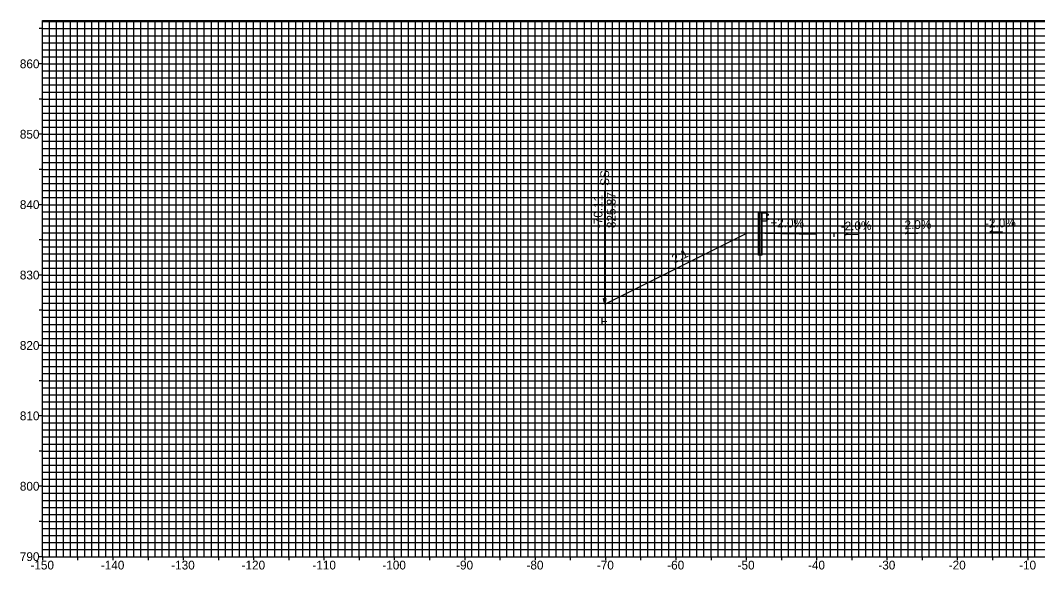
# Model space of a CAD drawing. Extents: x -153 to 153, y 788 to 866.
# Drawn here: x -153.1 to -8.6, y 788.2 to 866.2 of the extents above; entities that cross this region are included whole.
import ezdxf

# ---------------------------------------------------------------- set-up
doc = ezdxf.new("R2010")
doc.units = 0
for name, color, linetype in [('Exist Utilities Power Transformer CELL', 7, 'Continuous'), ('P_NCDOT_XS_Label_Grading_Side_Slope', 7, 'Continuous'), ('P_NCDOT_XS_Label_Slope_Superelevation', 7, 'Continuous'), ('P_NCDOT_XS_Leader_Line', 7, 'Continuous'), ('P_NCDOT_XS_Sheet_Annotation_Label', 7, 'Continuous'), ('P_NCDOT_XS_Sheet_Grid_Border', 7, 'Continuous'), ('P_NCDOT_XS_Slope_Label', 7, 'Continuous'), ('P_RDY_DXS_Guardrail_Cell', 7, 'Continuous'), ('P_RDY_XS_EOT_Tick_Mark', 7, 'Continuous'), ('Prop XS Label Slope Superelevation', 7, 'Continuous'), ('Sheet_Grid_Major', 7, 'Continuous'), ('Sheet_Grid_Middle', 7, 'Continuous'), ('Sheet_Grid_Minor', 7, 'Continuous')]:
    doc.layers.add(name, color=color, linetype=linetype)

msp = doc.modelspace()

# ---------------------------------------------------------------- linework, layer by layer
at = {"layer": 'Exist Utilities Power Transformer CELL'}
msp.add_lwpolyline([(-70.11, 825.87), (-49.83, 836.01), (-40, 835.81)], dxfattribs=at)
at = {"layer": 'P_NCDOT_XS_Leader_Line'}
msp.add_line((-70.11, 825.87), (-70.11, 842.07), dxfattribs=at)
msp.add_lwpolyline([(-70.11, 825.87), (-70.28, 826.69), (-69.93, 826.69)], close=True, dxfattribs=at)
at = {"layer": 'P_NCDOT_XS_Sheet_Grid_Border'}
for p, q in [((-150, 866.18), (150, 866.18)), ((-150, 790), (-150, 866.18)), ((-150, 790), (150, 790))]:
    msp.add_line(p, q, dxfattribs=at)
at = {"layer": 'P_RDY_DXS_Guardrail_Cell'}
for p, q in [((-47.77, 838.85), (-48.27, 838.85)), ((-48.27, 838.85), (-48.25, 838.85)), ((-48.27, 832.85), (-48.27, 838.85)), ((-48.25, 838.85), (-48.25, 832.85)), ((-47.78, 838.85), (-47.77, 838.85)), ((-47.78, 832.85), (-47.78, 838.85)), ((-47.77, 838.85), (-47.1, 838.85)), ((-47.77, 838.85), (-47.77, 832.85)), ((-47.1, 838.85), (-47.1, 837.68)), ((-47.1, 838.77), (-47.01, 838.75)), ((-46.86, 838.52), (-47.07, 838.38)), ((-47, 838.75), (-46.86, 838.65)), ((-47.1, 837.68), (-47.77, 837.68)), ((-47.1, 838.31), (-47.1, 838.26)), ((-47.1, 838.26), (-47.1, 838.22)), ((-47.01, 837.78), (-47.1, 837.76)), ((-47.07, 838.15), (-46.86, 838.01)), ((-46.86, 837.88), (-47, 837.78)), ((-47.77, 832.85), (-48.27, 832.85)), ((-48.25, 832.85), (-48.27, 832.85)), ((-47.77, 832.85), (-47.78, 832.85))]:
    msp.add_line(p, q, dxfattribs=at)
for centre, radius, start, end in [((-47.01, 838.72), 0.0328, 54.7024, 80), ((-46.9, 838.58), 0.0787, 304.6522, 54.7024), ((-47.02, 838.31), 0.0787, 124.6522, 179.98), ((-47.02, 838.22), 0.0787, 180.02, 235.3478), ((-47.01, 837.81), 0.0328, 280, 305.2976), ((-46.9, 837.94), 0.0787, 305.2976, 55.3478)]:
    msp.add_arc(centre, radius, start, end, dxfattribs=at)
at = {"layer": 'P_RDY_XS_EOT_Tick_Mark'}
msp.add_line((-37.5, 835.43), (-37.5, 836.05), dxfattribs=at)
at = {"layer": 'Prop XS Label Slope Superelevation'}
for p, q in [((-35.9, 835.7), (-35.56, 835.95)), ((-34.1, 835.74), (-35.9, 835.7)), ((-27.4, 835.87), (-27.06, 836.12)), ((-25.6, 835.91), (-27.4, 835.87)), ((-15.4, 836.11), (-15.06, 836.36)), ((-13.6, 836.15), (-15.4, 836.11))]:
    msp.add_line(p, q, dxfattribs=at)
at = {"layer": 'Sheet_Grid_Major'}
for p, q in [((-140, 790), (-140, 866.18)), ((-130, 790), (-130, 866.18)), ((-120, 790), (-120, 866.18)), ((-110, 790), (-110, 866.18)), ((-100, 790), (-100, 866.18)), ((-90, 790), (-90, 866.18)), ((-80, 790), (-80, 866.18)), ((-70, 790), (-70, 866.18)), ((-60, 790), (-60, 866.18)), ((-50, 790), (-50, 866.18)), ((-40, 790), (-40, 866.18)), ((-30, 790), (-30, 866.18)), ((-20, 790), (-20, 866.18)), ((-10, 790), (-10, 866.18)), ((-150, 860), (150, 860)), ((-150, 850), (150, 850)), ((-150, 840), (150, 840)), ((-150, 830), (150, 830)), ((-150, 820), (150, 820)), ((-150, 810), (150, 810)), ((-150, 800), (150, 800))]:
    msp.add_line(p, q, dxfattribs=at)
at = {"layer": 'Sheet_Grid_Middle'}
for p, q in [((-145, 790), (-145, 866.18)), ((-140, 790), (-140, 866.18)), ((-135, 790), (-135, 866.18)), ((-130, 790), (-130, 866.18)), ((-125, 790), (-125, 866.18)), ((-120, 790), (-120, 866.18)), ((-115, 790), (-115, 866.18)), ((-110, 790), (-110, 866.18)), ((-105, 790), (-105, 866.18)), ((-100, 790), (-100, 866.18)), ((-95, 790), (-95, 866.18)), ((-90, 790), (-90, 866.18)), ((-85, 790), (-85, 866.18)), ((-80, 790), (-80, 866.18)), ((-75, 790), (-75, 866.18)), ((-70, 790), (-70, 866.18)), ((-65, 790), (-65, 866.18)), ((-60, 790), (-60, 866.18)), ((-55, 790), (-55, 866.18)), ((-50, 790), (-50, 866.18)), ((-45, 790), (-45, 866.18)), ((-40, 790), (-40, 866.18)), ((-35, 790), (-35, 866.18)), ((-30, 790), (-30, 866.18)), ((-25, 790), (-25, 866.18)), ((-20, 790), (-20, 866.18)), ((-15, 790), (-15, 866.18)), ((-10, 790), (-10, 866.18)), ((-150, 865), (-150.48, 865)), ((-150, 865), (150, 865)), ((-150, 860), (-150.48, 860)), ((-150, 860), (150, 860)), ((-150, 855), (-150.48, 855)), ((-150, 855), (150, 855)), ((-150, 850), (-150.48, 850)), ((-150, 850), (150, 850)), ((-150, 845), (-150.48, 845)), ((-150, 845), (150, 845)), ((-150, 840), (-150.48, 840)), ((-150, 840), (150, 840)), ((-150, 835), (-150.48, 835)), ((-150, 835), (150, 835)), ((-150, 830), (-150.48, 830)), ((-150, 830), (150, 830)), ((-150, 825), (-150.48, 825)), ((-150, 825), (150, 825)), ((-150, 820), (-150.48, 820)), ((-150, 820), (150, 820)), ((-150, 815), (-150.48, 815)), ((-150, 815), (150, 815)), ((-150, 810), (-150.48, 810)), ((-150, 810), (150, 810)), ((-150, 805), (-150.48, 805)), ((-150, 805), (150, 805)), ((-150, 800), (-150.48, 800)), ((-150, 800), (150, 800)), ((-150, 795), (-150.48, 795)), ((-150, 795), (150, 795)), ((-150, 790), (-150.48, 790)), ((-150, 790), (-150, 789.52)), ((-145, 790), (-145, 789.52)), ((-140, 790), (-140, 789.52)), ((-135, 790), (-135, 789.52)), ((-130, 790), (-130, 789.52)), ((-125, 790), (-125, 789.52)), ((-120, 790), (-120, 789.52)), ((-115, 790), (-115, 789.52)), ((-110, 790), (-110, 789.52)), ((-105, 790), (-105, 789.52)), ((-100, 790), (-100, 789.52)), ((-95, 790), (-95, 789.52)), ((-90, 790), (-90, 789.52)), ((-85, 790), (-85, 789.52)), ((-80, 790), (-80, 789.52)), ((-75, 790), (-75, 789.52)), ((-70, 790), (-70, 789.52)), ((-65, 790), (-65, 789.52)), ((-60, 790), (-60, 789.52)), ((-55, 790), (-55, 789.52)), ((-50, 790), (-50, 789.52)), ((-45, 790), (-45, 789.52)), ((-40, 790), (-40, 789.52)), ((-35, 790), (-35, 789.52)), ((-30, 790), (-30, 789.52)), ((-25, 790), (-25, 789.52)), ((-20, 790), (-20, 789.52)), ((-15, 790), (-15, 789.52)), ((-10, 790), (-10, 789.52))]:
    msp.add_line(p, q, dxfattribs=at)
at = {"layer": 'Sheet_Grid_Minor'}
for p, q in [((-150, 866), (150, 866)), ((-149, 790), (-149, 866.18)), ((-148, 790), (-148, 866.18)), ((-147, 790), (-147, 866.18)), ((-146, 790), (-146, 866.18)), ((-144, 790), (-144, 866.18)), ((-143, 790), (-143, 866.18)), ((-142, 790), (-142, 866.18)), ((-141, 790), (-141, 866.18)), ((-139, 790), (-139, 866.18)), ((-138, 790), (-138, 866.18)), ((-137, 790), (-137, 866.18)), ((-136, 790), (-136, 866.18)), ((-134, 790), (-134, 866.18)), ((-133, 790), (-133, 866.18)), ((-132, 790), (-132, 866.18)), ((-131, 790), (-131, 866.18)), ((-129, 790), (-129, 866.18)), ((-128, 790), (-128, 866.18)), ((-127, 790), (-127, 866.18)), ((-126, 790), (-126, 866.18)), ((-124, 790), (-124, 866.18)), ((-123, 790), (-123, 866.18)), ((-122, 790), (-122, 866.18)), ((-121, 790), (-121, 866.18)), ((-119, 790), (-119, 866.18)), ((-118, 790), (-118, 866.18)), ((-117, 790), (-117, 866.18)), ((-116, 790), (-116, 866.18)), ((-114, 790), (-114, 866.18)), ((-113, 790), (-113, 866.18)), ((-112, 790), (-112, 866.18)), ((-111, 790), (-111, 866.18)), ((-109, 790), (-109, 866.18)), ((-108, 790), (-108, 866.18)), ((-107, 790), (-107, 866.18)), ((-106, 790), (-106, 866.18)), ((-104, 790), (-104, 866.18)), ((-103, 790), (-103, 866.18)), ((-102, 790), (-102, 866.18)), ((-101, 790), (-101, 866.18)), ((-99, 790), (-99, 866.18)), ((-98, 790), (-98, 866.18)), ((-97, 790), (-97, 866.18)), ((-96, 790), (-96, 866.18)), ((-94, 790), (-94, 866.18)), ((-93, 790), (-93, 866.18)), ((-92, 790), (-92, 866.18)), ((-91, 790), (-91, 866.18)), ((-89, 790), (-89, 866.18)), ((-88, 790), (-88, 866.18)), ((-87, 790), (-87, 866.18)), ((-86, 790), (-86, 866.18)), ((-84, 790), (-84, 866.18)), ((-83, 790), (-83, 866.18)), ((-82, 790), (-82, 866.18)), ((-81, 790), (-81, 866.18)), ((-79, 790), (-79, 866.18)), ((-78, 790), (-78, 866.18)), ((-77, 790), (-77, 866.18)), ((-76, 790), (-76, 866.18)), ((-74, 790), (-74, 866.18)), ((-73, 790), (-73, 866.18)), ((-72, 790), (-72, 866.18)), ((-71, 790), (-71, 866.18)), ((-69, 790), (-69, 866.18)), ((-68, 790), (-68, 866.18)), ((-67, 790), (-67, 866.18)), ((-66, 790), (-66, 866.18)), ((-64, 790), (-64, 866.18)), ((-63, 790), (-63, 866.18)), ((-62, 790), (-62, 866.18)), ((-61, 790), (-61, 866.18)), ((-59, 790), (-59, 866.18)), ((-58, 790), (-58, 866.18)), ((-57, 790), (-57, 866.18)), ((-56, 790), (-56, 866.18)), ((-54, 790), (-54, 866.18)), ((-53, 790), (-53, 866.18)), ((-52, 790), (-52, 866.18)), ((-51, 790), (-51, 866.18)), ((-49, 790), (-49, 866.18)), ((-48, 790), (-48, 866.18)), ((-47, 790), (-47, 866.18)), ((-46, 790), (-46, 866.18)), ((-44, 790), (-44, 866.18)), ((-43, 790), (-43, 866.18)), ((-42, 790), (-42, 866.18)), ((-41, 790), (-41, 866.18)), ((-39, 790), (-39, 866.18)), ((-38, 790), (-38, 866.18)), ((-37, 790), (-37, 866.18)), ((-36, 790), (-36, 866.18)), ((-34, 790), (-34, 866.18)), ((-33, 790), (-33, 866.18)), ((-32, 790), (-32, 866.18)), ((-31, 790), (-31, 866.18)), ((-29, 790), (-29, 866.18)), ((-28, 790), (-28, 866.18)), ((-27, 790), (-27, 866.18)), ((-26, 790), (-26, 866.18)), ((-24, 790), (-24, 866.18)), ((-23, 790), (-23, 866.18)), ((-22, 790), (-22, 866.18)), ((-21, 790), (-21, 866.18)), ((-19, 790), (-19, 866.18)), ((-18, 790), (-18, 866.18)), ((-17, 790), (-17, 866.18)), ((-16, 790), (-16, 866.18)), ((-14, 790), (-14, 866.18)), ((-13, 790), (-13, 866.18)), ((-12, 790), (-12, 866.18)), ((-11, 790), (-11, 866.18)), ((-9, 790), (-9, 866.18)), ((-150, 864), (150, 864)), ((-150, 863), (150, 863)), ((-150, 862), (150, 862)), ((-150, 861), (150, 861)), ((-150, 859), (150, 859)), ((-150, 858), (150, 858)), ((-150, 857), (150, 857)), ((-150, 856), (150, 856)), ((-150, 854), (150, 854)), ((-150, 853), (150, 853)), ((-150, 852), (150, 852)), ((-150, 851), (150, 851)), ((-150, 849), (150, 849)), ((-150, 848), (150, 848)), ((-150, 847), (150, 847)), ((-150, 846), (150, 846)), ((-150, 844), (150, 844)), ((-150, 843), (150, 843)), ((-150, 842), (150, 842)), ((-150, 841), (150, 841)), ((-150, 839), (150, 839)), ((-150, 838), (150, 838)), ((-150, 837), (150, 837)), ((-150, 836), (150, 836)), ((-150, 834), (150, 834)), ((-150, 833), (150, 833)), ((-150, 832), (150, 832)), ((-150, 831), (150, 831)), ((-150, 829), (150, 829)), ((-150, 828), (150, 828)), ((-150, 827), (150, 827)), ((-150, 826), (150, 826)), ((-150, 824), (150, 824)), ((-150, 823), (150, 823)), ((-150, 822), (150, 822)), ((-150, 821), (150, 821)), ((-150, 819), (150, 819)), ((-150, 818), (150, 818)), ((-150, 817), (150, 817)), ((-150, 816), (150, 816)), ((-150, 814), (150, 814)), ((-150, 813), (150, 813)), ((-150, 812), (150, 812)), ((-150, 811), (150, 811)), ((-150, 809), (150, 809)), ((-150, 808), (150, 808)), ((-150, 807), (150, 807)), ((-150, 806), (150, 806)), ((-150, 804), (150, 804)), ((-150, 803), (150, 803)), ((-150, 802), (150, 802)), ((-150, 801), (150, 801)), ((-150, 799), (150, 799)), ((-150, 798), (150, 798)), ((-150, 797), (150, 797)), ((-150, 796), (150, 796)), ((-150, 794), (150, 794)), ((-150, 793), (150, 793)), ((-150, 792), (150, 792)), ((-150, 791), (150, 791))]:
    msp.add_line(p, q, dxfattribs=at)

# ---------------------------------------------------------------- texts
at = {"layer": 'P_NCDOT_XS_Label_Grading_Side_Slope'}
for s, p in [('SS', (-69.48, 842.67)), ('-70.11', (-70.42, 836.67)), ('825.87', (-68.55, 836.67))]:
    msp.add_text(s, height=1.248, rotation=90, dxfattribs=at).set_placement(p)
msp.add_text('F', height=1.25, dxfattribs=at).set_placement((-70.71, 822.84))
at = {"layer": 'P_NCDOT_XS_Label_Slope_Superelevation'}
for p in [(-36.55, 836.33), (-28.05, 836.5), (-16.05, 836.74)]:
    msp.add_text('-2.0%', height=1.248, rotation=1.1458, dxfattribs=at).set_placement(p)
at = {"layer": 'P_NCDOT_XS_Sheet_Annotation_Label'}
for s, p in [('860', (-153.21, 859.38)), ('850', (-153.21, 849.38)), ('840', (-153.21, 839.38)), ('830', (-153.21, 829.38)), ('820', (-153.21, 819.38)), ('810', (-153.21, 809.38)), ('800', (-153.21, 799.38)), ('790', (-153.21, 789.38)), ('-150', (-151.7, 788.18)), ('-140', (-141.7, 788.18)), ('-130', (-131.7, 788.18)), ('-120', (-121.7, 788.18)), ('-110', (-111.64, 788.18)), ('-100', (-101.7, 788.18)), ('-90', (-91.22, 788.18)), ('-80', (-81.22, 788.18)), ('-70', (-71.22, 788.18)), ('-60', (-61.22, 788.18)), ('-50', (-51.22, 788.18)), ('-40', (-41.22, 788.18)), ('-30', (-31.22, 788.18)), ('-20', (-21.22, 788.18)), ('-10', (-11.22, 788.18))]:
    msp.add_text(s, height=1.248, dxfattribs=at).set_placement(p)
at = {"layer": 'P_NCDOT_XS_Slope_Label'}
for s, rotation, p in [('+2.0%', 358.8542, (-46.58, 836.82)), ('2:1', 26.5651, (-60.19, 831.63))]:
    msp.add_text(s, height=1.248, rotation=rotation, dxfattribs=at).set_placement(p)

doc.saveas('drawing.dxf')
